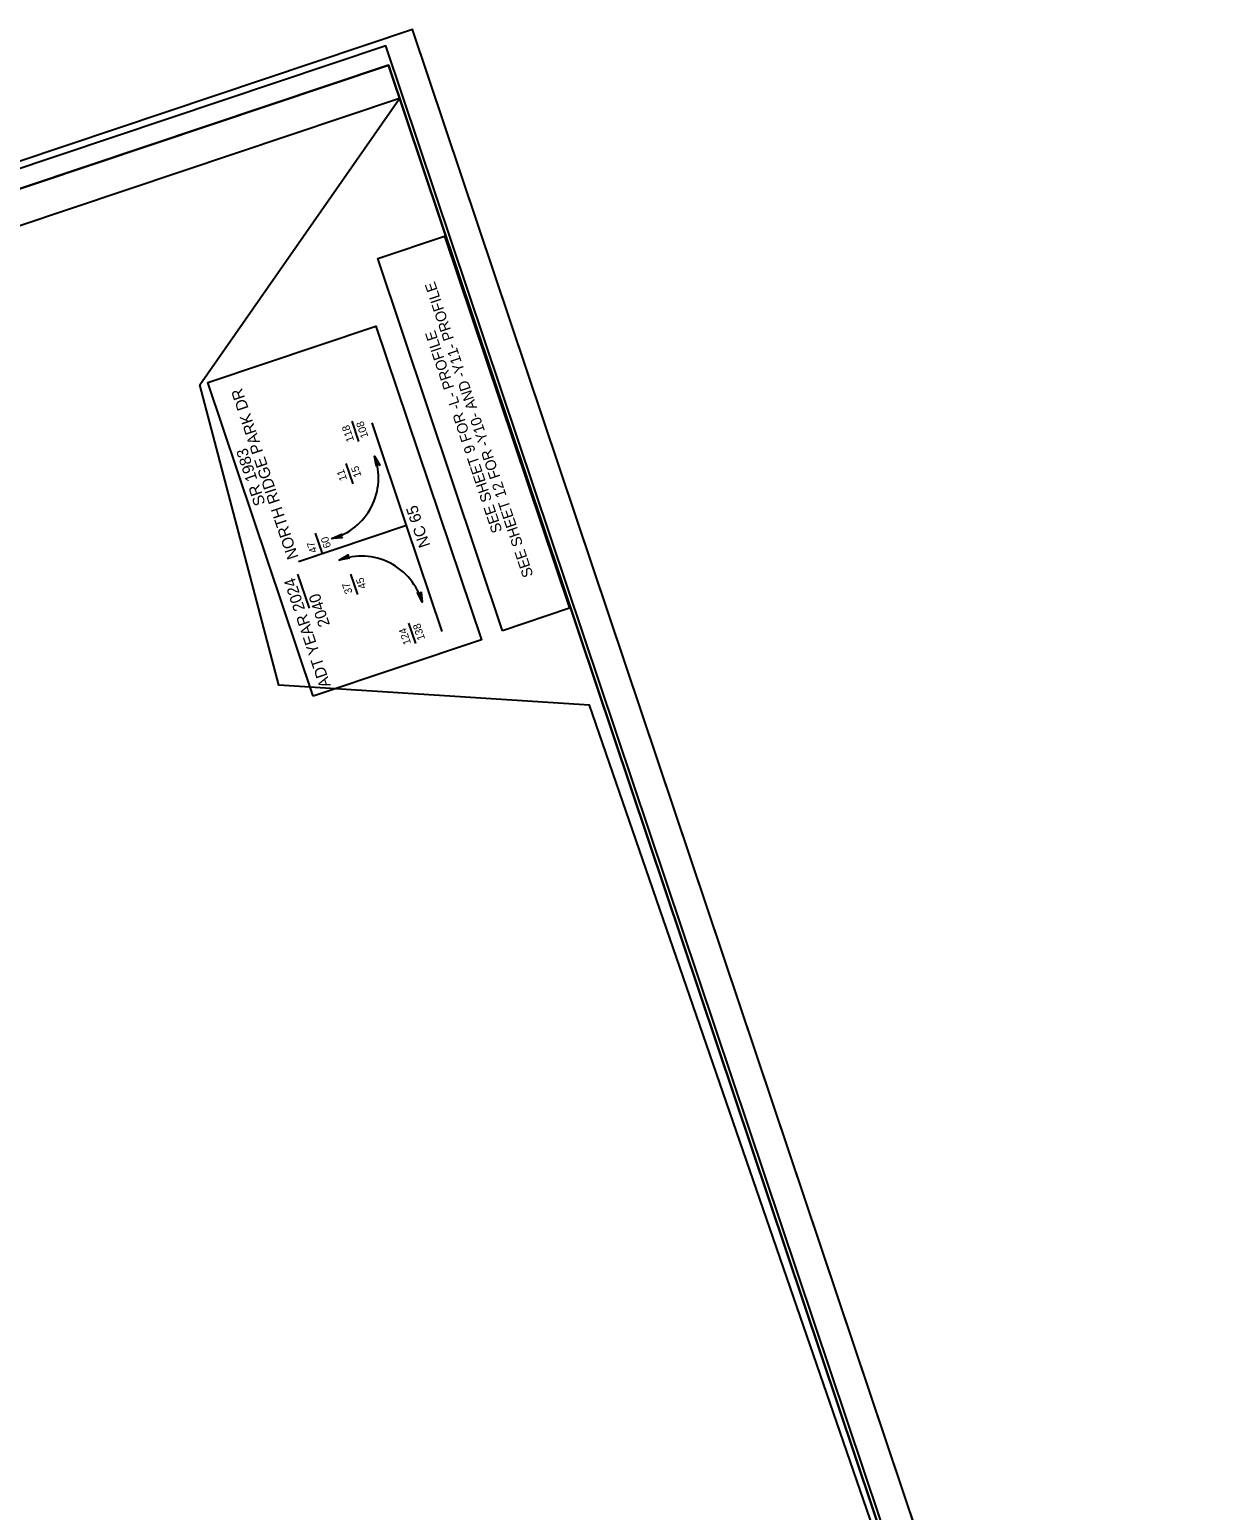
# Model space of a CAD drawing. Extents: x 1615436 to 1617010, y 903110 to 905055.
# Drawn here: x 1616223 to 1617010, y 904083 to 905055 of the extents above; entities that cross this region are included whole.
import ezdxf

# ---------------------------------------------------------------- set-up
doc = ezdxf.new("R2010")
doc.units = 0
for name, color, linetype in [('Exist Plan Preparation Drainage Flow Arrows', 7, 'Continuous'), ('Exist Plan Preparation Drainage Notes Label', 7, 'Continuous'), ('Exist Structure Minor Catch Basin', 7, 'Continuous'), ('Exist Structure Minor Pipes CMP 24 Inch Text', 7, 'Continuous'), ('Exist Structure Minor Pipes RCP 15 Inch', 7, 'Continuous'), ('Prop Drainage Structure Catch Basin Grate 840 03E CELL', 7, 'Continuous'), ('Scratch_Level_0', 7, 'Continuous'), ('Scratch_Level_8', 7, 'Continuous')]:
    doc.layers.add(name, color=color, linetype=linetype)

msp = doc.modelspace()

# ---------------------------------------------------------------- linework, layer by layer
at = {"layer": 'Exist Plan Preparation Drainage Flow Arrows'}
msp.add_lwpolyline([(1616986.86, 903464.68), (1616457.04, 905044.17), (1615456.82, 904708.68), (1615986.63, 903129.17)], close=True, dxfattribs=at)
at = {"layer": 'Exist Plan Preparation Drainage Notes Label'}
msp.add_lwpolyline([(1617009.96, 903458.71), (1616474.57, 905054.81), (1615436.42, 904706.58), (1615971.81, 903110.48)], close=True, dxfattribs=at)
at = {"layer": 'Exist Structure Minor Catch Basin'}
for p, q in [((1616439.35, 904784.47), (1616434.87, 904797.83)), ((1616470.6, 904729.22), (1616447.95, 904796.68)), ((1616435.48, 904756.67), (1616431, 904770.03)), ((1616470.6, 904729.22), (1616399.56, 904705.37)), ((1616493.97, 904659.57), (1616470.6, 904729.22)), ((1616415.37, 904710.92), (1616410.88, 904724.27)), ((1616406.78, 904675.08), (1616399.33, 904697.28)), ((1616438.54, 904684), (1616434.06, 904697.36)), ((1616476.56, 904651.73), (1616472.08, 904665.09))]:
    msp.add_line(p, q, dxfattribs=at)
msp.add_lwpolyline([(1616409.39, 904617.13), (1616340.25, 904823.13), (1616450.51, 904860.14), (1616519.66, 904654.14)], close=True, dxfattribs=at)
for centre, start, end in [((1616410.86, 904760.49), 285.13189, 20.24804), ((1616441.01, 904667.83), 15.6161, 110.73225)]:
    msp.add_arc(centre, 41.3, start, end, dxfattribs=at)
at = {"layer": 'Exist Structure Minor Pipes CMP 24 Inch Text'}
msp.add_line((1617009.96, 903458.71), (1616474.57, 905054.81), dxfattribs=at)
at = {"layer": 'Exist Structure Minor Pipes RCP 15 Inch'}
for points in [[(1616450.85, 904768.05), (1616449.61, 904774.78), (1616453.08, 904768.83), (1616451.66, 904769.22)], [(1616450.85, 904768.05), (1616449.61, 904774.78), (1616453.08, 904768.83), (1616451.66, 904769.22)], [(1616428.46, 904721.26), (1616421.64, 904720.62), (1616427.88, 904723.55), (1616427.36, 904722.16)], [(1616428.46, 904721.26), (1616421.64, 904720.62), (1616427.88, 904723.55), (1616427.36, 904722.16)], [(1616433.11, 904707.77), (1616426.39, 904706.46), (1616432.31, 904709.99), (1616431.93, 904708.56)], [(1616433.11, 904707.77), (1616426.39, 904706.46), (1616432.31, 904709.99), (1616431.93, 904708.56)], [(1616480.09, 904685.77), (1616480.79, 904678.95), (1616477.81, 904685.17), (1616479.2, 904684.66)], [(1616480.09, 904685.77), (1616480.79, 904678.95), (1616477.81, 904685.17), (1616479.2, 904684.66)]]:
    msp.add_lwpolyline(points, close=True, dxfattribs=at)
at = {"layer": 'Prop Drainage Structure Catch Basin Grate 840 03E CELL'}
msp.add_lwpolyline([(1616672.58, 903656.2), (1616919.77, 903656.8), (1616590.65, 904611.24), (1616386.84, 904624.44), (1616334.81, 904821.64), (1616466, 905009.57), (1615641.09, 904732.87), (1615700.02, 904557.19), (1615560.35, 904510.33), (1615954.19, 903336.21)], close=True, dxfattribs=at)
at = {"layer": 'Scratch_Level_0'}
msp.add_lwpolyline([(1616533.64, 904660.17), (1616451.69, 904904.48), (1616495.58, 904919.2), (1616577.53, 904674.89)], close=True, dxfattribs=at)
at = {"layer": 'Scratch_Level_8'}
for points in [[(1615463.14, 904697.64), (1615940.18, 903275.48), (1616935.67, 903609.4), (1616458.64, 905031.54)], [(1616935.67, 903609.4), (1615940.21, 903275.46), (1615526.76, 904507.95), (1615669.02, 904555.68), (1615605.42, 904745.34), (1616458.64, 905031.54)]]:
    msp.add_lwpolyline(points, close=True, dxfattribs=at)

# ---------------------------------------------------------------- texts
at = {"layer": 'Exist Structure Minor Catch Basin'}
for s, height, p in [('NORTH RIDGE PARK DR', 7.5, (1616399.79, 904708.46)), ('118', 5, (1616436.23, 904785.09)), ('108', 5, (1616445.6, 904787.61)), ('SR 1983', 7.5, (1616378.08, 904743.67)), ('11', 5, (1616431.61, 904759.53)), ('15', 5, (1616441.08, 904761.77)), ('NC 65', 7.5, (1616486.2, 904716.22)), ('47', 5, (1616412.03, 904712.16)), ('60', 5, (1616421.18, 904715.35)), ('ADT YEAR 2024', 7.5, (1616420.93, 904624.19)), ('37', 5, (1616435.21, 904685.24)), ('45', 5, (1616444.32, 904688.53)), ('   2040', 7.5, (1616423.04, 904656.22)), ('124', 5, (1616473.59, 904651.91)), ('138', 5, (1616482.81, 904654.86))]:
    msp.add_text(s, height=height, rotation=108.55478, dxfattribs=at).set_placement(p)
at = {"layer": 'Scratch_Level_0'}
for s, p in [('SEE SHEET 12 FOR -Y10- AND -Y11- PROFILE', (1616553.87, 904696.53)), ('SEE SHEET 9 FOR -L- PROFILE', (1616533.53, 904725.71))]:
    msp.add_text(s, height=7, rotation=108.54317, dxfattribs=at).set_placement(p)

doc.saveas('drawing.dxf')
